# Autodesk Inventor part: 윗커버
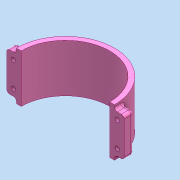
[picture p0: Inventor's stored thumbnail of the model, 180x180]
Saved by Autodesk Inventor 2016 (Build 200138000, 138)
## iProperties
Created: 2024-08
Part Number: 윗커버
Material: 일반
Document SubType Name: Modeling
Designer: pc-7
Density: 1 g/cm^3
Appearance: 기본값
Author: jhkim
Sending System: Autodesk Inventor 2025
Preprocessor: ST-DEVELOPER v20
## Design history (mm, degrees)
node "윗커버1"
node "솔리드2"
node "솔리드1"
